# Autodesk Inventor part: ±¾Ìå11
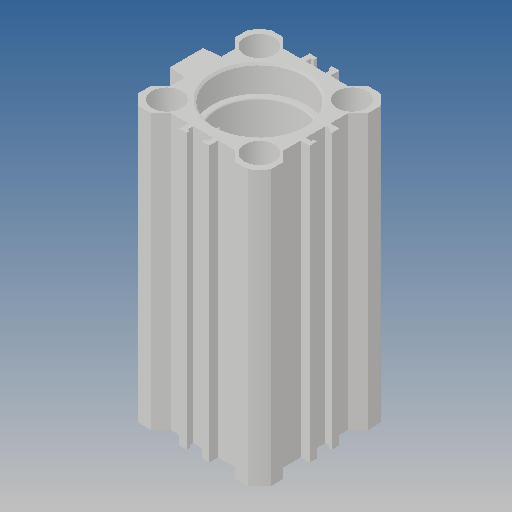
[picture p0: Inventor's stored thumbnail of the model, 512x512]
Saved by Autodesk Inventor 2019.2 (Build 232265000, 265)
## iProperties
Created: 2013-09
Part Number: ±¾Ìå11
Material: Ogólny
Document SubType Name: Modeling
Designer: CADENGINEERING4
Density: 1 g/cm^3
Appearance: Domyślna
Author: CADENGINEERING4
Revision Number: ÈÎºÎ
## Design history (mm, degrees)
feature "ÇÐ³ý-É¨Ãè2"
node "Bryła1"
